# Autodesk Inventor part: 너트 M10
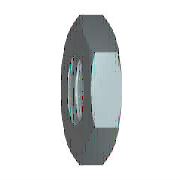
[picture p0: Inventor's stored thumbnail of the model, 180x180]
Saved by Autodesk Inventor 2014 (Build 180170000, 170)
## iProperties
IsCustomPart: 1
Created: 2012-02
Part Number: 너트 M10
Material: 강철, 연강
Description: 6각 가는 너트 - 이중 모따기
Document SubType Name: Modeling
Standard: JIS B 1181
Designer: mduedu
Standards Organization: JIS
Language: ko-KR
Size Designation: A/B M10
Categories: <MemberInstance><Categories><Category DisplayName="조임쇠" InternalName="e4da775c-781d-43d5-af7c-5136215cf5a6" Mnemonic="FSTN"><Category DisplayName="너트" InternalN
Density: 1 g/cm^3
Appearance: 주황색
Author: mduedu
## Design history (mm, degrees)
sketch "스케치1"
  geometry: L1 (-9.238, 0)-(-4.619, 8); L2 (-4.619, 8)-(4.619, 8); L3 (4.619, 8)-(9.238, 0); L4 (9.238, 0)-(4.619, -8); L5 (4.619, -8)-(-4.619, -8); L6 (-4.619, -8)-(-9.238, 0); 2 further points
  constraints: 12 end point, 1 coincident, 1 horizontal, 11 other
  dimensions: "d0" = 18.47521 distance of L3.end L1.start (= 1.1547 x SW)
extrude "본체" new body sketch "스케치1" distance "d1" = 5 (= KOH); taper "d2" = 0 deg
sketch "스케치2"
  geometry: L1 (0, 4.619)-(0, 9.238) reference; L2 (0, 9.238)-(5, 9.238) reference; L3 (5, 4.619)-(5, 9.238) reference; L4 (-1, 0)-(6, 0) reference; L5 (0.715, 9.238)-(0, 8); L6 (4.285, 9.238)-(5, 8)
  constraints: 4 end point, 4 point on line
  dimensions: "d3" = 30 deg angle of L1 L5 (= ANG1); "d4" = 30 deg angle of L3 L6 (= ANG2); "d5" = 16 diameter of L5.end L4 (= SW0); "d6" = 16 diameter of L6.end L4 (= SW01)
revolve "모따기1" sketch "스케치2" stored, may be unused: angle "d7" = 90 deg
sketch "스케치3"
  geometry: A1 r 8 centre (0, 0) between (-4, -6.928) and (4, -6.928) reference; 1 further point
  constraints: 1 coincident
hole "스레드" sketch "스케치3" at (0, 0) diameter "d25" = 8.376; stored, may be unused: countersink angle "d29" = 82 deg, drill point angle "d31" = 118 deg; dims "d26" = 6, "d27" = 4, "d28" = 2, "d30" = 8
workaxis "Work Axis1"
workplane "Work Plane1"
body "Solid1"
chamfer "모따기2" distance "d8" = 0.8119 (= -0.5 x GD1 + 0.5 x NND); stored, may be unused: angle "d9" = 30 deg, second distance "d40" = 0.8119 (= -0.5 x GD1 + 0.5 x NND)
chamfer "모따기3" distance "d10" = 0.8119 (= -0.5 x GD1 + 0.5 x NND); stored, may be unused: angle "d11" = 30 deg, second distance "d41" = 0.8119 (= -0.5 x GD1 + 0.5 x NND)
other parameters: "ANG1" = 30 deg [user parameter; used in 1 equation term], "ANG2" = 30 deg [user parameter; used in 1 equation term], "KOH" = 5 [user parameter; used in 1 equation term], "SW" = 16 [user parameter; used in 4 equation terms], "SW0" = 16 (= SW) [user parameter; used in 1 equation term], "SW01" = 16 (= SW) [user parameter; used in 1 equation term], "GD1" = 8.3762 (computed from THREADDIA, PTC, TOA) [user parameter; used in 4 equation terms], "d13" = 0, "d14" = 0, "d39" = 0, "d42" = 0, "GUL" = 0.8119 (= 0.541266 x PTC) [user parameter], "TPU" = 6.66667 (computed from PTC) [user parameter], "TOA" = 30 deg [user parameter; used in 1 equation term], "PTC" = 1.5 [user parameter; used in 4 equation terms], "E0" = 18.48 (= 1.155 x SW) [user parameter], "GAL" = 0.8119 (= 0.541266 x PTC) [user parameter]
